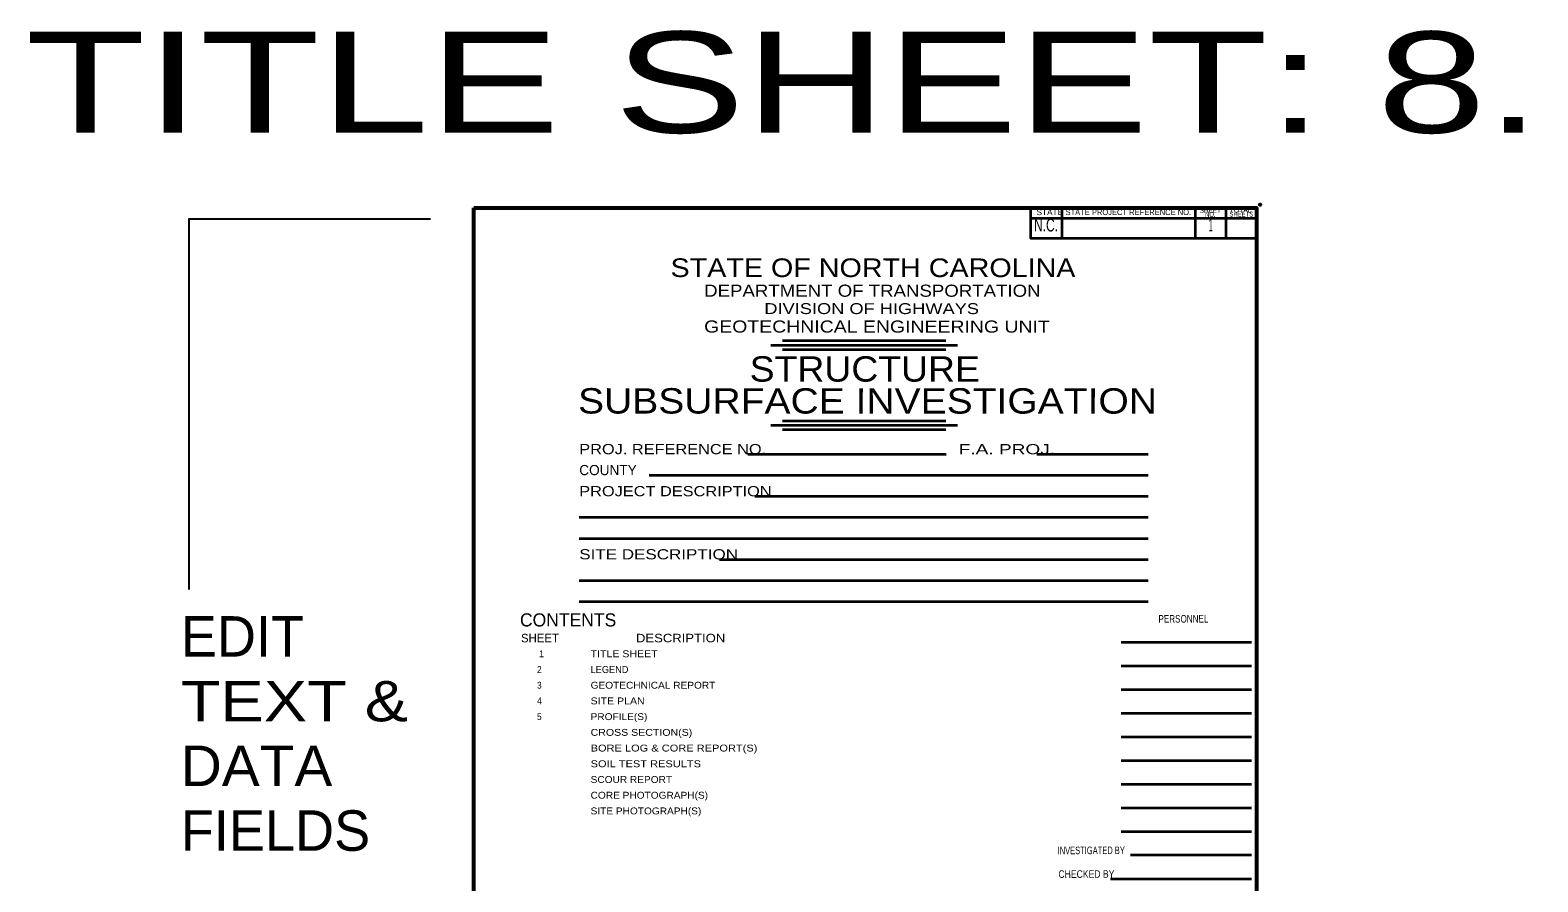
# Model space of a CAD drawing. Extents: x 278712 to 279914, y 171254 to 171792.
# Drawn here: x 278712.2 to 278861.3, y 171708.2 to 171792.4 of the extents above; entities that cross this region are included whole.
import ezdxf
from ezdxf.enums import TextEntityAlignment as Align

# ---------------------------------------------------------------- set-up
doc = ezdxf.new("R2010")
doc.units = 0
doc.header["$LTSCALE"] = 0.34
doc.header["$PDMODE"] = 32
doc.header["$PDSIZE"] = 0.17
doc.layers.add('60', color=7, linetype='Continuous', lineweight=35)
doc.layers.add('62', color=7, linetype='Continuous', lineweight=35)

msp = doc.modelspace()

# ---------------------------------------------------------------- linework, layer by layer
at = {"layer": '60'}
for p, q in [((278811.1684, 171773.8635), (278833.4716, 171773.8635)), ((278814.2104, 171774.8725), (278814.2104, 171771.8375)), ((278827.3894, 171774.8725), (278827.3894, 171771.8375)), ((278830.4304, 171774.8725), (278830.4304, 171771.8375)), ((278785.4574, 171761.3035), (278803.9024, 171761.3035)), ((278786.5929, 171761.7347), (278802.7669, 171761.7347)), ((278786.5929, 171760.8722), (278802.7669, 171760.8722)), ((278785.4574, 171753.3715), (278803.9024, 171753.3715)), ((278786.5929, 171753.8027), (278802.7669, 171753.8027)), ((278786.5929, 171752.9402), (278802.7669, 171752.9402)), ((278783.1686, 171750.508), (278802.7846, 171750.508)), ((278811.7519, 171750.502), (278822.7666, 171750.502)), ((278773.4279, 171748.4347), (278822.7666, 171748.4347)), ((278783.8504, 171746.3492), (278822.7666, 171746.3492)), ((278766.5076, 171744.2675), (278822.7666, 171744.2675)), ((278766.5071, 171742.183), (278822.7666, 171742.183)), ((278780.3599, 171740.107), (278822.7674, 171740.107)), ((278766.5086, 171738.0252), (278822.7674, 171738.0252)), ((278766.5081, 171735.9407), (278822.7674, 171735.9407)), ((278820.0716, 171731.9327), (278832.9676, 171731.9327)), ((278820.0716, 171729.5927), (278832.9676, 171729.5927)), ((278820.0716, 171727.2527), (278832.9676, 171727.2527)), ((278820.0716, 171724.9127), (278832.9676, 171724.9127)), ((278820.0716, 171722.5727), (278832.9676, 171722.5727)), ((278820.0716, 171720.2327), (278832.9676, 171720.2327)), ((278820.0716, 171717.8927), (278832.9676, 171717.8927)), ((278820.0716, 171715.5527), (278832.9676, 171715.5527)), ((278820.0716, 171713.2127), (278832.9676, 171713.2127)), ((278821.0209, 171710.8727), (278832.9676, 171710.8727)), ((278819.0329, 171708.5277), (278832.9676, 171708.5277))]:
    msp.add_line(p, q, dxfattribs=at)
at = {"layer": '60', "lineweight": 53}
msp.add_lwpolyline([(278756.0874, 171774.8725), (278833.4716, 171774.8725), (278833.4716, 171671.7172), (278756.0874, 171671.7172)], close=True, dxfattribs=at)
at = {"layer": '60'}
msp.add_lwpolyline([(278811.1684, 171774.8725), (278833.4716, 171774.8725), (278833.4716, 171771.8375), (278811.1684, 171771.8375)], close=True, dxfattribs=at)
at = {"layer": '60', "lineweight": 25}
msp.add_lwpolyline([(278727.9286, 171737.1167), (278727.9286, 171773.7802), (278751.7901, 171773.7802)], dxfattribs=at)
at = {"layer": '60'}
msp.add_point((278833.8216, 171775.1775), dxfattribs=at)

# ---------------------------------------------------------------- texts
for s, height, rotation, width, p in [('N.C.', 1.271, 0.015, 0.7, (278812.658, 171772.5298)), ('STATE', 0.5824, 0.015, 1.05, (278813.0317, 171774.1498)), ('STATE PROJECT REFERENCE NO.', 0.5824, 0.015, 0.8, (278820.7937, 171774.1519)), ('SHEET', 0.4992, 0.015, 0.75, (278828.8982, 171774.3787)), ('NO.', 0.4992, 0.015, 0.7, (278828.9044, 171773.9766)), ('TOTAL', 0.4992, 0.015, 0.85, (278831.9008, 171774.4077)), ('SHEETS', 0.4992, 0.015, 0.7, (278831.9659, 171774.0017)), ('1', 1.255, 0.015, 0.45, (278828.9412, 171772.5425)), ('STATE OF NORTH CAROLINA', 1.845, 359.987, 1.15, (278795.5488, 171768.0212)), ('DEPARTMENT OF TRANSPORTATION', 1.198, 359.987, 1.15, (278795.4836, 171766.077)), ('DIVISION OF HIGHWAYS', 1.078, 359.987, 1.25, (278795.4166, 171764.3639)), ('GEOTECHNICAL ENGINEERING UNIT', 1.198, 359.987, 1.2, (278795.9421, 171762.5307)), ('STRUCTURE', 2.509, 359.987, 1.1, (278794.7372, 171757.6807)), ('SUBSURFACE INVESTIGATION', 2.509, 359.987, 1.15, (278795.0058, 171754.5221))]:
    msp.add_text(s, height=height, rotation=rotation, dxfattribs=dict(at, width=width)).set_placement(p, align=Align.CENTER)
for s, height, rotation, width, p in [('PROJ. REFERENCE NO.', 1.006, 359.987, 1.2, (278766.5069, 171750.5095)), ('F.A. PROJ.', 1.006, 359.987, 1.4, (278804.0276, 171750.5045)), ('PROJECT DESCRIPTION', 1.006, 359.987, 1.2, (278766.5054, 171746.3507)), ('SITE DESCRIPTION', 1.006, 359.987, 1.25, (278766.5061, 171740.1087)), ('PERSONNEL', 0.7488, 0.132, 0.8, (278823.7726, 171733.8497)), ('INVESTIGATED BY', 0.7488, 0.132, 0.65, (278813.8049, 171710.9497)), ('CHECKED BY', 0.7488, 0.132, 0.85, (278813.8849, 171708.6097))]:
    msp.add_text(s, height=height, rotation=rotation, dxfattribs=dict(at, width=width)).set_placement(p)
msp.add_text('COUNTY', height=1.006, rotation=359.987, dxfattribs=at).set_placement((278766.5061, 171748.4352))
for s, height, p in [('EDIT', 4, (278727.1064, 171730.491)), ('LEGEND', 0.68, (278767.6276, 171728.8762)), ('FIELDS', 4, (278727.1064, 171711.291))]:
    msp.add_text(s, height=height, dxfattribs=at).set_placement(p)
msp.add_text('CONTENTS', height=1.295, rotation=359.992, dxfattribs=at).set_placement((278765.405, 171733.4737), align=Align.CENTER)
for s, height, p in [('SHEET', 0.84, (278762.6154, 171731.9042)), ('1', 0.68, (278762.7779, 171730.4302))]:
    msp.add_text(s, height=height, dxfattribs=at).set_placement(p, align=Align.CENTER)
for s, height, width, p in [('DESCRIPTION', 0.84, 1.15, (278776.5275, 171731.9042)), ('2', 0.68, 0.9, (278762.5577, 171728.8762)), ('3', 0.68, 0.9, (278762.5577, 171727.3222)), ('4', 0.68, 0.95, (278762.5739, 171725.7682)), ('5', 0.68, 0.9, (278762.5577, 171724.2142))]:
    msp.add_text(s, height=height, dxfattribs=dict(at, width=width)).set_placement(p, align=Align.CENTER)
for s, height, width, p in [('TITLE SHEET', 0.68, 1.15, (278767.6276, 171730.4302)), ('TEXT &', 4, 1.2, (278727.1064, 171724.091)), ('GEOTECHNICAL REPORT', 0.68, 1.1, (278767.6276, 171727.3222)), ('SITE PLAN', 0.68, 1.15, (278767.6276, 171725.7682)), ('PROFILE(S)', 0.68, 1.1, (278767.6276, 171724.2142)), ('CROSS SECTION(S)', 0.68, 1.15, (278767.6276, 171722.6602)), ('DATA', 4, 1.05, (278727.1064, 171717.691)), ('BORE LOG & CORE REPORT(S)', 0.68, 1.2, (278767.6276, 171721.1062)), ('SOIL TEST RESULTS', 0.68, 1.2, (278767.6276, 171719.5522)), ('SCOUR REPORT', 0.68, 1.1, (278767.6276, 171717.9982)), ('CORE PHOTOGRAPH(S)', 0.68, 1.1, (278767.6276, 171716.4442)), ('SITE PHOTOGRAPH(S)', 0.68, 1.1, (278767.6276, 171714.8902))]:
    msp.add_text(s, height=height, dxfattribs=dict(at, width=width)).set_placement(p)
at = {"layer": '62', "width": 1.45}
msp.add_text('TITLE SHEET: 8.5" x 11"', height=10, dxfattribs=at).set_placement((278711.7764, 171782.2915))

doc.saveas('drawing.dxf')
